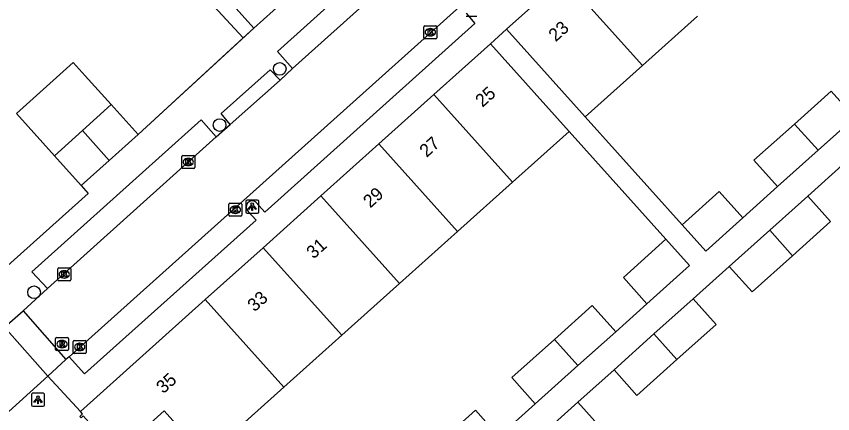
# Model space of a CAD drawing. Extents: x 162172 to 163187, y 382874 to 383684.
# Drawn here: x 162811.9 to 162874.9, y 383471.7 to 383502.4 of the extents above; entities that cross this region are included whole.
import ezdxf

# ---------------------------------------------------------------- set-up
doc = ezdxf.new("R2010")
doc.units = 0
for name, color, linetype in [('IMGEO_Boom', 7, 'Continuous'), ('IMGEO_Kolk', 7, 'Continuous'), ('IMGEO_Lichtpunt', 7, 'Continuous'), ('IMGEO_Muur', 7, 'Continuous'), ('IMGEO_Pand', 7, 'Continuous'), ('IMGEO_Pand_nummerreeks', 7, 'Continuous'), ('IMGEO_Rijbaan_lokaal_open', 7, 'Continuous'), ('IMGEO_Rioolput', 7, 'Continuous'), ('IMGEO_Voetpad_open', 7, 'Continuous')]:
    doc.layers.add(name, color=color, linetype=linetype)

msp = doc.modelspace()

# ---------------------------------------------------------------- linework, layer by layer
at = {"layer": 'IMGEO_Boom'}
for centre in [(162832.234, 383498.336), (162827.582, 383493.999), (162813.262, 383481.086)]:
    msp.add_circle(centre, 0.489, dxfattribs=at)
at = {"layer": 'IMGEO_Kolk'}
for p, q in [((162843.355, 383500.741), (162843.355, 383501.593)), ((162843.43, 383501.667), (162844.282, 383501.667)), ((162843.843, 383501.447), (162843.868, 383501.447)), ((162844.356, 383501.593), (162844.356, 383500.741)), ((162843.866, 383500.887), (162843.841, 383500.887)), ((162844.282, 383500.667), (162843.43, 383500.667)), ((162824.663, 383490.716), (162824.663, 383491.568)), ((162824.738, 383491.642), (162825.59, 383491.642)), ((162825.151, 383491.422), (162825.176, 383491.422)), ((162825.664, 383491.568), (162825.664, 383490.716)), ((162825.174, 383490.862), (162825.149, 383490.862)), ((162825.59, 383490.642), (162824.738, 383490.642)), ((162828.302, 383487.03), (162828.302, 383487.882)), ((162828.377, 383487.956), (162829.229, 383487.956)), ((162828.79, 383487.736), (162828.815, 383487.736)), ((162829.303, 383487.882), (162829.303, 383487.03)), ((162829.229, 383486.956), (162828.377, 383486.956)), ((162828.813, 383487.176), (162828.788, 383487.176)), ((162815.095, 383482.038), (162815.095, 383482.89)), ((162815.17, 383482.964), (162816.022, 383482.964)), ((162815.583, 383482.744), (162815.608, 383482.744)), ((162816.096, 383482.89), (162816.096, 383482.038)), ((162816.022, 383481.964), (162815.17, 383481.964)), ((162815.606, 383482.184), (162815.581, 383482.184)), ((162816.295, 383476.441), (162816.295, 383477.293)), ((162816.37, 383477.367), (162817.222, 383477.367)), ((162816.783, 383477.147), (162816.808, 383477.147)), ((162817.296, 383477.293), (162817.296, 383476.441)), ((162817.222, 383476.367), (162816.37, 383476.367)), ((162816.806, 383476.587), (162816.781, 383476.587))]:
    msp.add_line(p, q, dxfattribs=at)
for points in [[(162843.355, 383500.741), (162843.355, 383501.593)], [(162843.43, 383501.667), (162844.282, 383501.667)], [(162844.356, 383501.593), (162844.356, 383500.741)], [(162843.676, 383501.367), (162843.799, 383501.367), (162843.799, 383501.216), (162843.929, 383501.367), (162844.093, 383501.367), (162843.947, 383501.216), (162844.1, 383500.967), (162843.948, 383500.967), (162843.863, 383501.131), (162843.799, 383501.064), (162843.799, 383500.967), (162843.676, 383500.967), (162843.676, 383501.367)], [(162844.282, 383500.667), (162843.43, 383500.667)], [(162824.663, 383490.716), (162824.663, 383491.568)], [(162824.738, 383491.642), (162825.59, 383491.642)], [(162824.984, 383491.342), (162825.107, 383491.342), (162825.107, 383491.191), (162825.237, 383491.342), (162825.401, 383491.342), (162825.255, 383491.191), (162825.408, 383490.942), (162825.256, 383490.942), (162825.171, 383491.106), (162825.107, 383491.039), (162825.107, 383490.942), (162824.984, 383490.942), (162824.984, 383491.342)], [(162825.664, 383491.568), (162825.664, 383490.716)], [(162825.59, 383490.642), (162824.738, 383490.642)], [(162828.302, 383487.03), (162828.302, 383487.882)], [(162828.377, 383487.956), (162829.229, 383487.956)], [(162828.623, 383487.656), (162828.746, 383487.656), (162828.746, 383487.505), (162828.876, 383487.656), (162829.04, 383487.656), (162828.894, 383487.505), (162829.047, 383487.256), (162828.895, 383487.256), (162828.81, 383487.42), (162828.746, 383487.353), (162828.746, 383487.256), (162828.623, 383487.256), (162828.623, 383487.656)], [(162829.303, 383487.882), (162829.303, 383487.03)], [(162829.229, 383486.956), (162828.377, 383486.956)], [(162815.095, 383482.038), (162815.095, 383482.89)], [(162815.17, 383482.964), (162816.022, 383482.964)], [(162815.416, 383482.664), (162815.539, 383482.664), (162815.539, 383482.513), (162815.669, 383482.664), (162815.833, 383482.664), (162815.687, 383482.513), (162815.84, 383482.264), (162815.688, 383482.264), (162815.603, 383482.428), (162815.539, 383482.361), (162815.539, 383482.264), (162815.416, 383482.264), (162815.416, 383482.664)], [(162816.096, 383482.89), (162816.096, 383482.038)], [(162816.022, 383481.964), (162815.17, 383481.964)], [(162816.295, 383476.441), (162816.295, 383477.293)], [(162816.37, 383477.367), (162817.222, 383477.367)], [(162816.616, 383477.067), (162816.739, 383477.067), (162816.739, 383476.916), (162816.869, 383477.067), (162817.033, 383477.067), (162816.887, 383476.916), (162817.04, 383476.667), (162816.888, 383476.667), (162816.803, 383476.831), (162816.739, 383476.764), (162816.739, 383476.667), (162816.616, 383476.667), (162816.616, 383477.067)], [(162817.296, 383477.293), (162817.296, 383476.441)], [(162817.222, 383476.367), (162816.37, 383476.367)]]:
    msp.add_lwpolyline(points, dxfattribs=at)
for centre, start, end in [((162843.432, 383501.591), 91.55205, 178.44795), ((162843.432, 383501.591), 91.55205, 178.44795), ((162844.28, 383501.591), 1.55205, 88.44795), ((162844.28, 383501.591), 1.55205, 88.44795), ((162843.432, 383500.743), 181.55205, 268.44795), ((162843.432, 383500.743), 181.55205, 268.44795), ((162844.28, 383500.743), 271.55205, 358.44795), ((162844.28, 383500.743), 271.55205, 358.44795), ((162824.74, 383491.566), 91.55205, 178.44795), ((162824.74, 383491.566), 91.55205, 178.44795), ((162825.588, 383491.566), 1.55205, 88.44795), ((162825.588, 383491.566), 1.55205, 88.44795), ((162824.74, 383490.718), 181.55205, 268.44795), ((162824.74, 383490.718), 181.55205, 268.44795), ((162825.588, 383490.718), 271.55205, 358.44795), ((162825.588, 383490.718), 271.55205, 358.44795), ((162828.379, 383487.88), 91.55205, 178.44795), ((162828.379, 383487.88), 91.55205, 178.44795), ((162829.227, 383487.88), 1.55205, 88.44795), ((162829.227, 383487.88), 1.55205, 88.44795), ((162828.379, 383487.032), 181.55205, 268.44795), ((162828.379, 383487.032), 181.55205, 268.44795), ((162829.227, 383487.032), 271.55205, 358.44795), ((162829.227, 383487.032), 271.55205, 358.44795), ((162815.172, 383482.888), 91.55205, 178.44795), ((162815.172, 383482.888), 91.55205, 178.44795), ((162816.02, 383482.888), 1.55205, 88.44795), ((162816.02, 383482.888), 1.55205, 88.44795), ((162815.172, 383482.04), 181.55205, 268.44795), ((162815.172, 383482.04), 181.55205, 268.44795), ((162816.02, 383482.04), 271.55205, 358.44795), ((162816.02, 383482.04), 271.55205, 358.44795), ((162816.372, 383477.291), 91.55205, 178.44795), ((162816.372, 383477.291), 91.55205, 178.44795), ((162817.22, 383477.291), 1.55205, 88.44795), ((162817.22, 383477.291), 1.55205, 88.44795), ((162816.372, 383476.443), 181.55205, 268.44795), ((162816.372, 383476.443), 181.55205, 268.44795), ((162817.22, 383476.443), 271.55205, 358.44795), ((162817.22, 383476.443), 271.55205, 358.44795)]:
    msp.add_arc(centre, 0.0765, start, end, dxfattribs=at)
for centre, major_axis, ratio, start_param, end_param in [((162843.842, 383501.167), (-0.387, 0.002), 0.722429, 4.712389, 7.853982), ((162843.867, 383501.167), (-0.39, 0.002), 0.717154, 1.570796, 4.712389), ((162825.15, 383491.142), (-0.387, 0.002), 0.722429, 4.712389, 7.853982), ((162825.175, 383491.142), (-0.39, 0.002), 0.717154, 1.570796, 4.712389), ((162828.789, 383487.456), (-0.387, 0.002), 0.722429, 4.712389, 7.853982), ((162828.814, 383487.456), (-0.39, 0.002), 0.717154, 1.570796, 4.712389), ((162815.582, 383482.464), (-0.387, 0.002), 0.722429, 4.712389, 7.853982), ((162815.607, 383482.464), (-0.39, 0.002), 0.717154, 1.570796, 4.712389), ((162816.782, 383476.867), (-0.387, 0.002), 0.722429, 4.712389, 7.853982), ((162816.807, 383476.867), (-0.39, 0.002), 0.717154, 1.570796, 4.712389)]:
    msp.add_ellipse(centre, major_axis=major_axis, ratio=ratio, start_param=start_param, end_param=end_param, dxfattribs=at)
at = {"layer": 'IMGEO_Lichtpunt'}
for p, q in [((162846.626, 383502.394), (162847.434, 383502.394)), ((162846.626, 383502.394), (162847.434, 383502.394)), ((162830.514, 383488.188), (162829.706, 383488.188)), ((162830.514, 383488.188), (162829.706, 383488.188)), ((162829.612, 383488.093), (162829.612, 383487.286)), ((162829.612, 383488.093), (162829.612, 383487.286)), ((162830.608, 383487.286), (162830.608, 383488.093)), ((162830.608, 383487.286), (162830.608, 383488.093)), ((162829.706, 383487.192), (162830.514, 383487.192)), ((162829.706, 383487.192), (162830.514, 383487.192)), ((162813.069, 383473.186), (162813.069, 383472.379)), ((162813.069, 383473.186), (162813.069, 383472.379)), ((162813.971, 383473.281), (162813.163, 383473.281)), ((162813.971, 383473.281), (162813.163, 383473.281)), ((162814.065, 383472.379), (162814.065, 383473.186)), ((162814.065, 383472.379), (162814.065, 383473.186)), ((162813.163, 383472.285), (162813.971, 383472.285)), ((162813.163, 383472.285), (162813.971, 383472.285))]:
    msp.add_line(p, q, dxfattribs=at)
for points in [[(162829.986, 383487.757), (162830.025, 383487.729), (162829.837, 383487.467), (162829.799, 383487.494), (162829.986, 383487.757)], [(162830.088, 383487.709), (162830.135, 383487.709), (162830.135, 383487.387), (162830.088, 383487.387), (162830.088, 383487.709)], [(162830.198, 383487.729), (162830.236, 383487.756), (162830.423, 383487.494), (162830.384, 383487.466), (162830.198, 383487.729)], [(162813.443, 383472.85), (162813.482, 383472.822), (162813.294, 383472.56), (162813.256, 383472.587), (162813.443, 383472.85)], [(162813.545, 383472.802), (162813.592, 383472.802), (162813.592, 383472.48), (162813.545, 383472.48), (162813.545, 383472.802)], [(162813.655, 383472.822), (162813.693, 383472.849), (162813.88, 383472.587), (162813.841, 383472.559), (162813.655, 383472.822)]]:
    msp.add_lwpolyline(points, dxfattribs=at)
for centre in [(162830.111, 383487.891), (162813.568, 383472.984)]:
    msp.add_circle(centre, 0.0994, dxfattribs=at)
for centre, start, end in [((162829.706, 383488.093), 90, 180), ((162829.706, 383488.093), 90, 180), ((162830.514, 383488.093), 0, 90), ((162830.514, 383488.093), 0, 90), ((162829.706, 383487.286), 180, 270), ((162829.706, 383487.286), 180, 270), ((162830.514, 383487.286), 270, 0), ((162830.514, 383487.286), 270, 360), ((162813.163, 383473.186), 90, 180), ((162813.163, 383473.186), 90, 180), ((162813.971, 383473.186), 0, 90), ((162813.971, 383473.186), 0, 90), ((162813.163, 383472.379), 180, 270), ((162813.163, 383472.379), 180, 270), ((162813.971, 383472.379), 270, 0), ((162813.971, 383472.379), 270, 360)]:
    msp.add_arc(centre, 0.0946, start, end, dxfattribs=at)
at = {"layer": 'IMGEO_Muur'}
for points in [[(162821.299, 383493.269), (162830.227, 383501.489)], [(162816.911, 383489.325), (162817.43, 383488.716), (162810.976, 383482.915)]]:
    msp.add_lwpolyline(points, dxfattribs=at)
at = {"layer": 'IMGEO_Pand'}
for points in [[(162830.227, 383501.489), (162824.225, 383508.179)], [(162834.707, 383505.515), (162830.227, 383501.489)], [(162849.743, 383501.392), (162854.17, 383505.363)], [(162854.17, 383505.363), (162860.236, 383498.607)], [(162864.477, 383502.415), (162860.236, 383498.607)], [(162855.809, 383494.632), (162849.743, 383501.392)], [(162844.118, 383496.351), (162848.491, 383500.277)], [(162848.491, 383500.277), (162854.564, 383493.512)], [(162814.839, 383491.631), (162811.907, 383494.895), (162816.295, 383498.838), (162817.222, 383497.806), (162819.227, 383495.575)], [(162860.236, 383498.607), (162855.809, 383494.632)], [(162876.611, 383494.59), (162874.791, 383496.617), (162871.962, 383494.078)], [(162839.876, 383492.543), (162844.118, 383496.351)], [(162850.191, 383489.586), (162844.118, 383496.351)], [(162816.996, 383493.57), (162819.227, 383495.575)], [(162819.227, 383495.575), (162821.299, 383493.269)], [(162873.783, 383492.051), (162876.611, 383494.59)], [(162870.657, 383489.245), (162868.837, 383491.273), (162871.962, 383494.078)], [(162871.962, 383494.078), (162873.783, 383492.051)], [(162814.839, 383491.631), (162816.996, 383493.57)], [(162819.068, 383491.264), (162816.996, 383493.57)], [(162821.299, 383493.269), (162819.068, 383491.264)], [(162854.564, 383493.512), (162850.191, 383489.586)], [(162835.412, 383488.534), (162839.876, 383492.543)], [(162839.876, 383492.543), (162845.949, 383485.778)], [(162870.657, 383489.245), (162873.783, 383492.051)], [(162816.911, 383489.325), (162814.839, 383491.631)], [(162819.068, 383491.264), (162816.911, 383489.325)], [(162850.191, 383489.586), (162845.949, 383485.778)], [(162863.289, 383486.294), (162866.145, 383488.858), (162867.966, 383486.83)], [(162830.947, 383484.526), (162835.412, 383488.534)], [(162835.412, 383488.534), (162841.485, 383481.769)], [(162872.985, 383488.514), (162870.05, 383485.88)], [(162872.985, 383488.514), (162874.756, 383486.541), (162871.821, 383483.907)], [(162863.289, 383486.294), (162865.11, 383484.266), (162867.966, 383486.83)], [(162845.949, 383485.778), (162841.485, 383481.769)], [(162870.05, 383485.88), (162866.934, 383483.085)], [(162871.821, 383483.907), (162870.05, 383485.88)], [(162862.046, 383485.179), (162858.759, 383482.229), (162860.58, 383480.201)], [(162860.58, 383480.201), (162863.867, 383483.15), (162862.046, 383485.179)], [(162826.482, 383480.518), (162830.947, 383484.526)], [(162830.947, 383484.526), (162837.02, 383477.761)], [(162871.821, 383483.907), (162868.706, 383481.112), (162866.934, 383483.085)], [(162841.485, 383481.769), (162837.02, 383477.761)], [(162816.859, 383471.878), (162826.482, 383480.518)], [(162832.555, 383473.753), (162826.482, 383480.518)], [(162858.177, 383478.023), (162856.346, 383480.063), (162853.429, 383477.446)], [(162864.144, 383480.58), (162861.119, 383477.866)], [(162864.144, 383480.58), (162865.916, 383478.608), (162862.89, 383475.893)], [(162837.02, 383477.761), (162832.555, 383473.753)], [(162855.25, 383475.418), (162858.177, 383478.023)], [(162861.119, 383477.866), (162858.033, 383475.097)], [(162862.89, 383475.893), (162861.119, 383477.866)], [(162853.429, 383477.446), (162850.139, 383474.492), (162851.959, 383472.465)], [(162853.429, 383477.446), (162855.25, 383475.418)], [(162862.89, 383475.893), (162859.805, 383473.124), (162858.033, 383475.097)], [(162851.959, 383472.465), (162855.25, 383475.418)], [(162832.555, 383473.753), (162829.059, 383470.614)], [(162855.239, 383472.59), (162852.187, 383469.851)], [(162855.239, 383472.59), (162857.011, 383470.617), (162853.959, 383467.878)], [(162819.646, 383468.641), (162817.051, 383471.532), (162816.898, 383471.388), (162816.8, 383471.491), (162817.017, 383471.695), (162816.859, 383471.878)], [(162819.646, 383468.641), (162823.301, 383471.92), (162826.266, 383468.631), (162822.612, 383465.352)], [(162846.132, 383467.236), (162844.312, 383469.264), (162847.332, 383471.974), (162849.152, 383469.946)]]:
    msp.add_lwpolyline(points, dxfattribs=at)
at = {"layer": 'IMGEO_Rijbaan_lokaal_open'}
for points in [[(162833.213, 383498.368), (162856.866, 383519.569)], [(162815.972, 383476.091), (162860.073, 383515.696)], [(162832.253, 383497.468), (162833.213, 383498.368)], [(162828.412, 383494.046), (162832.253, 383497.468)], [(162827.325, 383493.083), (162828.412, 383494.046)], [(162814.293, 383481.374), (162827.325, 383493.083)], [(162812.415, 383479.642), (162814.293, 383481.374)], [(162810.977, 383478.382), (162812.415, 383479.642)], [(162812.415, 383479.642), (162815.714, 383475.898)], [(162814.328, 383474.613), (162810.977, 383478.382)], [(162815.714, 383475.898), (162814.328, 383474.613)], [(162815.972, 383476.091), (162815.714, 383475.898)], [(162814.328, 383474.613), (162798.454, 383460.252)]]:
    msp.add_lwpolyline(points, dxfattribs=at)
at = {"layer": 'IMGEO_Rioolput'}
for p, q in [((162814.925, 383476.654), (162814.925, 383477.506)), ((162815, 383477.58), (162815.852, 383477.58)), ((162815.926, 383477.506), (162815.926, 383476.654)), ((162815.413, 383477.36), (162815.438, 383477.36)), ((162815.852, 383476.58), (162815, 383476.58)), ((162815.436, 383476.8), (162815.411, 383476.8))]:
    msp.add_line(p, q, dxfattribs=at)
for points in [[(162814.925, 383476.654), (162814.925, 383477.506)], [(162815, 383477.58), (162815.852, 383477.58)], [(162815.926, 383477.506), (162815.926, 383476.654)], [(162815.514, 383477.278), (162815.262, 383477.28), (162815.262, 383476.88)], [(162815.262, 383476.88), (162815.386, 383476.88), (162815.386, 383477.042), (162815.397, 383477.042)], [(162815.44, 383477.199), (162815.386, 383477.199), (162815.386, 383477.118)], [(162815.386, 383477.118), (162815.438, 383477.118)], [(162815.444, 383477.013), (162815.515, 383476.88), (162815.655, 383476.88), (162815.59, 383477.006)], [(162815.852, 383476.58), (162815, 383476.58)]]:
    msp.add_lwpolyline(points, dxfattribs=at)
for centre, radius, start, end in [((162815.002, 383477.504), 0.0765, 91.55205, 178.44795), ((162815.002, 383477.504), 0.0765, 91.55205, 178.44795), ((162815.85, 383477.504), 0.0765, 1.55205, 88.44795), ((162815.85, 383477.504), 0.0765, 1.55205, 88.44795), ((162815.396, 383476.989), 0.0533, 26.02933, 88.69889), ((162815.422, 383477.307), 0.19, 274.7715, 282.96867), ((162815.446, 383477.103), 0.0964, 77.00612, 93.18647), ((162815.46, 383477.16), 0.0378, 276.66336, 79.67722), ((162815.513, 383477.168), 0.109, 350.36119, 89.41601), ((162815.511, 383477.168), 0.112, 277.58423, 350.98172), ((162815.495, 383476.953), 0.108, 29.51342, 73.79051), ((162815.002, 383476.656), 0.0765, 181.55205, 268.44795), ((162815.002, 383476.656), 0.0765, 181.55205, 268.44795), ((162815.85, 383476.656), 0.0765, 271.55205, 358.44795), ((162815.85, 383476.656), 0.0765, 271.55205, 358.44795)]:
    msp.add_arc(centre, radius, start, end, dxfattribs=at)
for centre, major_axis, ratio, start_param, end_param in [((162815.412, 383477.08), (-0.387, 0.002), 0.722429, 4.712389, 7.853982), ((162815.437, 383477.08), (-0.39, 0.002), 0.717154, 1.570796, 4.712389)]:
    msp.add_ellipse(centre, major_axis=major_axis, ratio=ratio, start_param=start_param, end_param=end_param, dxfattribs=at)
at = {"layer": 'IMGEO_Voetpad_open'}
for points in [[(162829.409, 383500.736), (162825.19, 383505.317), (162800.917, 383532.162)], [(162833.213, 383498.368), (162832.049, 383499.676), (162846.044, 383512.284), (162846.714, 383511.569)], [(162846.62, 383502.649), (162847.298, 383501.852), (162831.068, 383487.264), (162830.407, 383488.023)], [(162830.227, 383501.489), (162829.409, 383500.736)], [(162849.743, 383501.392), (162848.491, 383500.277)], [(162829.409, 383500.736), (162821.299, 383493.269)], [(162828.412, 383494.046), (162827.701, 383494.887), (162831.491, 383498.267), (162832.253, 383497.468)], [(162855.809, 383494.632), (162863.289, 383486.294)], [(162814.293, 383481.374), (162813.102, 383482.651), (162826.154, 383494.4), (162827.325, 383493.083)], [(162854.564, 383493.512), (162862.046, 383485.179)], [(162875.898, 383491.127), (162872.985, 383488.514)], [(162816.911, 383489.325), (162817.43, 383488.716), (162810.976, 383482.915)], [(162867.966, 383486.83), (162870.657, 383489.245)], [(162829.798, 383487.324), (162830.422, 383486.653), (162817.156, 383474.785), (162815.972, 383476.091)], [(162866.934, 383483.085), (162864.144, 383480.58)], [(162860.58, 383480.201), (162858.177, 383478.023)], [(162858.033, 383475.097), (162855.239, 383472.59)], [(162814.328, 383474.613), (162816.859, 383471.878)], [(162851.959, 383472.465), (162849.152, 383469.946)]]:
    msp.add_lwpolyline(points, dxfattribs=at)
msp.add_arc((162830.104, 383487.673), 0.464, 49.12151, 228.75082, dxfattribs=at)

# ---------------------------------------------------------------- texts
at = {"layer": 'IMGEO_Pand_nummerreeks'}
for s, rotation, p in [('23', 41.89957, (162853.532, 383500.386)), ('25', 41.91659, (162847.88, 383495.322)), ('27', 41.91659, (162843.572, 383491.455)), ('29', 41.91659, (162839.219, 383487.547)), ('31', 41.91659, (162834.84, 383483.613)), ('33', 41.91659, (162830.29, 383479.53)), ('35', 41.91659, (162823.246, 383473.207))]:
    msp.add_text(s, height=1, rotation=rotation, dxfattribs=at).set_placement(p)

doc.saveas('drawing.dxf')
